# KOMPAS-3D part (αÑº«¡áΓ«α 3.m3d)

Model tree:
1. Эскиз:1
2. Операция выдавливания:1
     Толщина стенки 1 = 2; Толщина стенки 2 = 8; Расстояние 1 = 1
3. Эскиз:3
4. Операция выдавливания:2
     Толщина стенки 1 = 2; Толщина стенки 2 = 6; Расстояние 1 = 5
5. Эскиз:4
6. Операция выдавливания:3
     Толщина стенки 1 = 2; Толщина стенки 2 = 6; Расстояние 1 = 1
7. Эскиз:5
8. Эскиз:6
9. Операция выдавливания:4
     Толщина стенки 1 = 2; Толщина стенки 2 = 2.5; Расстояние 1 = 50
10. Эскиз:7
11. Вырезать элемент выдавливания:1
     Толщина стенки 2 = 1.5; Расстояние 1 = 40
12. Эскиз:8
13. Операция выдавливания:5
     Толщина стенки 1 = 2; Толщина стенки 2 = 2.5; Расстояние 1 = 50
14. Эскиз:9
15. Вырезать элемент выдавливания:2
     Толщина стенки 2 = 1.5; Расстояние 1 = 40
16. Эскиз:10
17. Операция выдавливания:6
     Толщина стенки 1 = 2; Толщина стенки 2 = 2.5; Расстояние 1 = 10
18. Эскиз:11
19. Операция выдавливания:7
     Толщина стенки 1 = 2; Толщина стенки 2 = 6; Расстояние 1 = 1
20. Эскиз:12
21. Операция выдавливания:8
     Толщина стенки 1 = 2; Толщина стенки 2 = 6; Расстояние 1 = 5
22. Эскиз:13
23. Операция выдавливания:9
     Толщина стенки 1 = 2; Толщина стенки 2 = 8; Расстояние 1 = 1
24. Эскиз:14
25. Вырезать элемент выдавливания:3
     Толщина стенки 2 = 1.5; Расстояние 1 = 23
26. Эскиз:15
27. Вырезать элемент выдавливания:4
     Толщина стенки 2 = 1.5; Расстояние 1 = 1
28. Эскиз:16
29. Вырезать элемент выдавливания:5
     Расстояние 1 = 150
30. Эскиз:17
31. Операция выдавливания:10
     Толщина стенки 1 = 7; Расстояние 1 = 10; Расстояние 2 = 0.4
